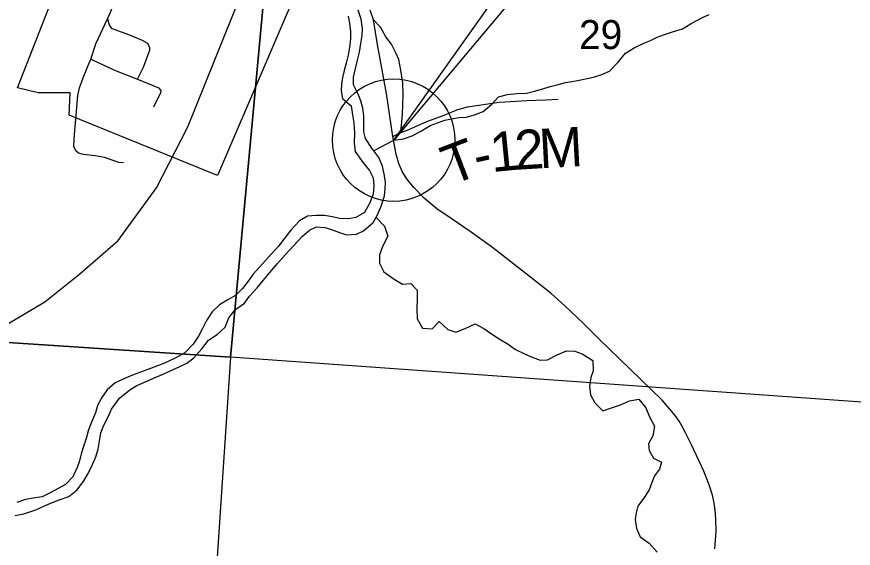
# Model space of a CAD drawing. Extents: x 0 to 34, y 0 to 22.
# Drawn here: x 5.937 to 7.144, y 16.597 to 17.363 of the extents above; entities that cross this region are included whole.
import ezdxf

# ---------------------------------------------------------------- set-up
doc = ezdxf.new("R2010")
doc.units = 0
for name, color, linetype in [('GM_X_City_Street', 7, 'Continuous'), ('GM_X_Corporation', 7, 'Continuous'), ('GM_X_Major_River', 7, 'Continuous'), ('GM_X_Minor_River', 7, 'Continuous'), ('GM_X_Rail_Line', 7, 'Continuous'), ('GM_X_Section', 7, 'Continuous'), ('GM_X_Section_Text', 7, 'Continuous'), ('GM_X_State_Route', 7, 'Continuous'), ('GM_X_Township_Road', 7, 'Continuous'), ('GM_X_Township_Road_Text', 7, 'Continuous'), ('SH_Text', 7, 'Continuous')]:
    doc.layers.add(name, color=color, linetype=linetype)

msp = doc.modelspace()

# ---------------------------------------------------------------- linework, layer by layer
at = {"layer": 'GM_X_City_Street'}
for points in [[(6.022, 17.2152), (6.0252, 17.2494), (6.0273, 17.2604), (6.0326, 17.2748), (6.0396, 17.2917), (6.0438, 17.3016), (6.0512, 17.3236), (6.0681, 17.3597), (6.0704, 17.365), (6.0721, 17.3696), (6.0854, 17.4017), (6.0922, 17.4205), (6.0947, 17.4305)], [(6.0681, 17.3597), (6.0702, 17.3512), (6.0734, 17.3466), (6.0784, 17.3443), (6.0981, 17.3371), (6.1177, 17.3289), (6.1255, 17.3246), (6.1285, 17.3183), (6.1285, 17.3136)], [(6.1114, 17.2731), (6.1198, 17.2904), (6.1285, 17.3136)], [(6.0438, 17.3016), (6.0806, 17.2851), (6.1114, 17.2731), (6.1194, 17.2695), (6.1325, 17.2644), (6.1416, 17.2602), (6.1446, 17.2566), (6.1443, 17.253), (6.1344, 17.2327)]]:
    msp.add_lwpolyline(points, dxfattribs=at)
at = {"layer": 'GM_X_Corporation'}
msp.add_lwpolyline([(6.2264, 17.1339), (6.0126, 17.2209), (6.0141, 17.2532), (5.9678, 17.2531), (5.9382, 17.2604), (6.023, 17.4781), (5.8434, 17.5552), (5.9039, 17.7022), (5.952, 17.6811), (6.1661, 18.1773), (6.6117, 17.9917), (6.5173, 17.6859), (6.5005, 17.6619), (6.4701, 17.6297), (6.4392, 17.6123), (6.4283, 17.605)], close=True, dxfattribs=at)
at = {"layer": 'GM_X_Major_River'}
for points in [[(5.9345, 16.6439), (5.947, 16.6464), (5.9645, 16.652), (5.9771, 16.6576), (5.9869, 16.6621), (5.998, 16.6665), (6.012, 16.6714), (6.0242, 16.6808), (6.0338, 16.694), (6.0399, 16.7042), (6.0465, 16.7174), (6.0511, 16.7284), (6.0542, 16.7397), (6.0566, 16.7511), (6.0585, 16.7632), (6.0624, 16.7742), (6.0693, 16.787), (6.0739, 16.7973), (6.085, 16.8131), (6.0999, 16.8251), (6.1102, 16.8315), (6.1239, 16.8371), (6.1334, 16.8416), (6.149, 16.8483), (6.1616, 16.8539), (6.1711, 16.858), (6.1821, 16.8636), (6.1924, 16.8711), (6.2042, 16.8843), (6.2138, 16.8968), (6.226, 16.905), (6.2374, 16.9156), (6.2428, 16.9288), (6.2524, 16.9409), (6.2654, 16.9499), (6.2726, 16.9601), (6.2837, 16.9721), (6.2925, 16.9827), (6.3021, 16.994), (6.3132, 17.0072), (6.3242, 17.0197), (6.3361, 17.0325), (6.3491, 17.0464), (6.3594, 17.0554), (6.3693, 17.0599), (6.3814, 17.0591), (6.3912, 17.056), (6.4026, 17.0517), (6.4128, 17.0486), (6.4272, 17.0492), (6.4371, 17.0541), (6.4509, 17.0661), (6.457, 17.0763), (6.4628, 17.0896), (6.4674, 17.1047), (6.4686, 17.1146), (6.4687, 17.1244), (6.4672, 17.1362), (6.4647, 17.1476), (6.4591, 17.1598), (6.4493, 17.1735), (6.4399, 17.1873), (6.4377, 17.1971), (6.4378, 17.2195), (6.4364, 17.2313), (6.4334, 17.2416), (6.4293, 17.2511), (6.4226, 17.2648), (6.4226, 17.2758), (6.4258, 17.2883), (6.4285, 17.3004), (6.4312, 17.3118), (6.4332, 17.3243), (6.4352, 17.336), (6.4356, 17.3459), (6.4338, 17.3596), (6.4294, 17.3721)], [(6.4153, 17.3635), (6.4171, 17.3536), (6.4185, 17.3415), (6.4185, 17.3316), (6.4176, 17.3217), (6.4153, 17.3077), (6.4122, 17.296), (6.4091, 17.2854), (6.4067, 17.2755), (6.4055, 17.2661), (6.4051, 17.2562), (6.4069, 17.2452), (6.4193, 17.2345), (6.4215, 17.2215), (6.423, 17.2098), (6.424, 17.1954), (6.4239, 17.1806), (6.425, 17.1684), (6.4351, 17.1543), (6.446, 17.1413), (6.4509, 17.1307), (6.4523, 17.1196), (6.4511, 17.1071), (6.4457, 17.0935), (6.4384, 17.0807), (6.4259, 17.0735), (6.416, 17.0717), (6.4027, 17.0722), (6.3925, 17.0742), (6.3807, 17.0762), (6.369, 17.0762), (6.3565, 17.0752), (6.3447, 17.0688), (6.3324, 17.0553), (6.3221, 17.0421), (6.3145, 17.0319), (6.2996, 17.0157), (6.2877, 17.0025), (6.2782, 16.9919), (6.2709, 16.9817), (6.2625, 16.9712), (6.2525, 16.961), (6.2404, 16.9543), (6.2293, 16.9475), (6.219, 16.9377), (6.2106, 16.9249), (6.2044, 16.9124), (6.199, 16.9022), (6.1914, 16.8909), (6.1795, 16.8784), (6.1655, 16.8706), (6.1502, 16.8635), (6.1297, 16.856), (6.1168, 16.8508), (6.1042, 16.846), (6.0913, 16.8408), (6.0791, 16.8352), (6.0673, 16.825), (6.0596, 16.8141), (6.0535, 16.8023), (6.0504, 16.7917), (6.045, 16.7785), (6.0404, 16.7675), (6.0369, 16.7547), (6.0338, 16.7448), (6.0299, 16.7327), (6.0276, 16.7229), (6.0241, 16.713), (6.0179, 16.6998), (6.0072, 16.6885), (5.9977, 16.6832), (5.9851, 16.6765), (5.9737, 16.6709), (5.9608, 16.6691), (5.9494, 16.6669), (5.9369, 16.6624)]]:
    msp.add_lwpolyline(points, dxfattribs=at)
at = {"layer": 'GM_X_Minor_River'}
for points in [[(6.452, 17.1697), (6.4554, 17.1716), (6.469, 17.1789), (6.4807, 17.185), (6.4947, 17.1869), (6.5076, 17.1911), (6.5208, 17.1983), (6.5332, 17.206), (6.5544, 17.2136), (6.5643, 17.2159), (6.5752, 17.2174), (6.5851, 17.2182), (6.5975, 17.2217), (6.61, 17.2262), (6.6225, 17.2369), (6.6319, 17.2475), (6.6448, 17.251), (6.6584, 17.2521), (6.6724, 17.2529), (6.6837, 17.2556), (6.6958, 17.2587), (6.7064, 17.2621), (6.7166, 17.2648), (6.7284, 17.2679), (6.7382, 17.2694), (6.7484, 17.2713), (6.7689, 17.2759), (6.781, 17.2797), (6.7919, 17.2843), (6.8044, 17.2976), (6.8153, 17.3105), (6.8278, 17.3182), (6.8414, 17.3246), (6.8512, 17.3288), (6.861, 17.3334), (6.8712, 17.3372), (6.8845, 17.3418), (6.8973, 17.3453), (6.9098, 17.3532), (6.926, 17.3616), (6.9359, 17.3662)], [(6.4553, 17.0735), (6.4675, 17.0609), (6.4724, 17.0465), (6.4649, 17.0325), (6.4604, 17.0196), (6.4605, 17.0075), (6.4666, 16.9953), (6.4814, 16.9848), (6.4935, 16.9772), (6.5056, 16.9784), (6.5147, 16.9685), (6.5148, 16.956), (6.514, 16.9416), (6.5145, 16.9272), (6.5221, 16.9139), (6.5361, 16.9128), (6.5463, 16.9235), (6.5588, 16.9121), (6.5702, 16.908), (6.5838, 16.9133), (6.5982, 16.9202), (6.611, 16.9134), (6.6205, 16.9066), (6.633, 16.8987), (6.6459, 16.8907), (6.6566, 16.8832), (6.6683, 16.8775), (6.6782, 16.873), (6.6918, 16.8677), (6.7028, 16.8681), (6.7164, 16.8754), (6.73, 16.8815), (6.7421, 16.8807), (6.7527, 16.877), (6.7679, 16.8671), (6.7687, 16.8524), (6.7653, 16.8429), (6.7631, 16.8303), (6.7647, 16.8178), (6.7708, 16.8061), (6.7825, 16.7947), (6.795, 16.7989), (6.8079, 16.8035), (6.8211, 16.8093), (6.8343, 16.8116), (6.8446, 16.7991), (6.8496, 16.7862), (6.8568, 16.7729), (6.8546, 16.7589), (6.8482, 16.7471), (6.8493, 16.7377), (6.8554, 16.7267), (6.8672, 16.7206), (6.8642, 16.7108), (6.857, 16.7009), (6.8529, 16.6914), (6.8491, 16.6808), (6.8409, 16.6682), (6.8329, 16.6572), (6.8307, 16.6477), (6.8292, 16.6379), (6.8308, 16.625), (6.8365, 16.6129), (6.8494, 16.6038), (6.8608, 16.5909)]]:
    msp.add_lwpolyline(points, dxfattribs=at)
at = {"layer": 'GM_X_Rail_Line'}
msp.add_lwpolyline([(5.1686, 16.7396), (5.2381, 16.7552), (5.4076, 16.7935), (5.6302, 16.838), (5.761, 16.8642), (5.834, 16.8816), (5.9075, 16.9106), (5.9775, 16.9517), (6.0279, 16.9921), (6.0831, 17.0404), (6.1385, 17.1164), (6.1838, 17.204), (6.3397, 17.5908), (6.4017, 17.7369), (6.4258, 17.8052), (6.4372, 17.8653), (6.4459, 17.9321), (6.4566, 18.0231), (6.4686, 18.0692), (6.4811, 18.1076), (6.5022, 18.1582), (6.5679, 18.2873), (6.8025, 18.728)], dxfattribs=at)
at = {"layer": 'GM_X_Section'}
for points in [[(5.3412, 17.9492), (6.3391, 17.8836), (6.2455, 16.872), (5.2673, 16.9365)], [(6.3391, 17.8836), (7.3065, 17.8168), (7.2305, 16.8022), (6.2455, 16.872)], [(6.2455, 16.872), (6.2183, 16.4683), (6.1917, 16.0616), (6.1792, 15.8658), (5.1915, 15.9177), (5.2673, 16.9365)]]:
    msp.add_lwpolyline(points, close=True, dxfattribs=at)
at = {"layer": 'GM_X_State_Route'}
msp.add_lwpolyline([(6.9441, 16.5957), (6.9458, 16.621), (6.9456, 16.639), (6.9443, 16.6516), (6.943, 16.6616), (6.9407, 16.6732), (6.9358, 16.6882), (6.9282, 16.7078), (6.9105, 16.7459), (6.9014, 16.7638), (6.8966, 16.7731), (6.8923, 16.7801), (6.8894, 16.7845), (6.8866, 16.7879), (6.879, 16.7972), (6.8678, 16.8101), (6.7768, 16.8986), (6.7552, 16.9201), (6.7276, 16.9459), (6.7081, 16.9638), (6.6764, 16.9888), (6.6232, 17.03), (6.5909, 17.0532), (6.5649, 17.0711), (6.5432, 17.0861), (6.5254, 17.1009), (6.51, 17.1166), (6.4996, 17.1292), (6.4931, 17.1398), (6.488, 17.1514), (6.4844, 17.1647), (6.4796, 17.1902), (6.4703, 17.252), (6.4576, 17.3227), (6.4516, 17.3585), (6.4466, 17.3724)], dxfattribs=at)
at = {"layer": 'GM_X_Township_Road'}
for points in [[(6.491, 17.196), (6.4933, 17.2218), (6.4946, 17.2509), (6.4937, 17.2674), (6.491, 17.286), (6.488, 17.3014), (6.484, 17.3109), (6.4777, 17.3231), (6.4696, 17.3341), (6.4618, 17.3479), (6.4516, 17.3585)], [(6.4796, 17.1902), (6.491, 17.196), (6.5026, 17.2004), (6.5286, 17.2118), (6.5537, 17.2211), (6.5717, 17.2285), (6.5873, 17.233), (6.6329, 17.2397), (6.6729, 17.242), (6.7001, 17.2431), (6.7178, 17.2439)], [(6.0911, 17.1523), (6.0844, 17.1527), (6.0744, 17.1563), (6.0634, 17.1599), (6.0503, 17.1624), (6.0332, 17.1641), (6.0263, 17.1664), (6.022, 17.1698), (6.0195, 17.1757), (6.0197, 17.1873), (6.022, 17.2152)]]:
    msp.add_lwpolyline(points, dxfattribs=at)
at = {"layer": 'SH_Text'}
msp.add_lwpolyline([(6.4807, 17.185), (7.1921, 18.186), (7.3213, 18.186), (6.4807, 17.185)], close=True, dxfattribs=at)
msp.add_circle((6.4807, 17.185), 0.0883, dxfattribs=at)

# ---------------------------------------------------------------- texts
at = {"layer": 'GM_X_Section_Text'}
msp.add_text('29', height=0.04186, rotation=0, dxfattribs=at).set_placement((6.7481, 17.3162))
at = {"layer": 'GM_X_Township_Road_Text'}
for s, rotation, p in [('1', 5.6764, (6.6225, 17.1388)), ('2', 3.4264, (6.6568, 17.1422)), ('M', 3.0435, (6.6916, 17.1443)), ('T', 20.9252, (6.5639, 17.1195)), ('-', 12.23, (6.6014, 17.1341))]:
    msp.add_text(s, height=0.0568, rotation=rotation, dxfattribs=at).set_placement(p)

doc.saveas('drawing.dxf')
